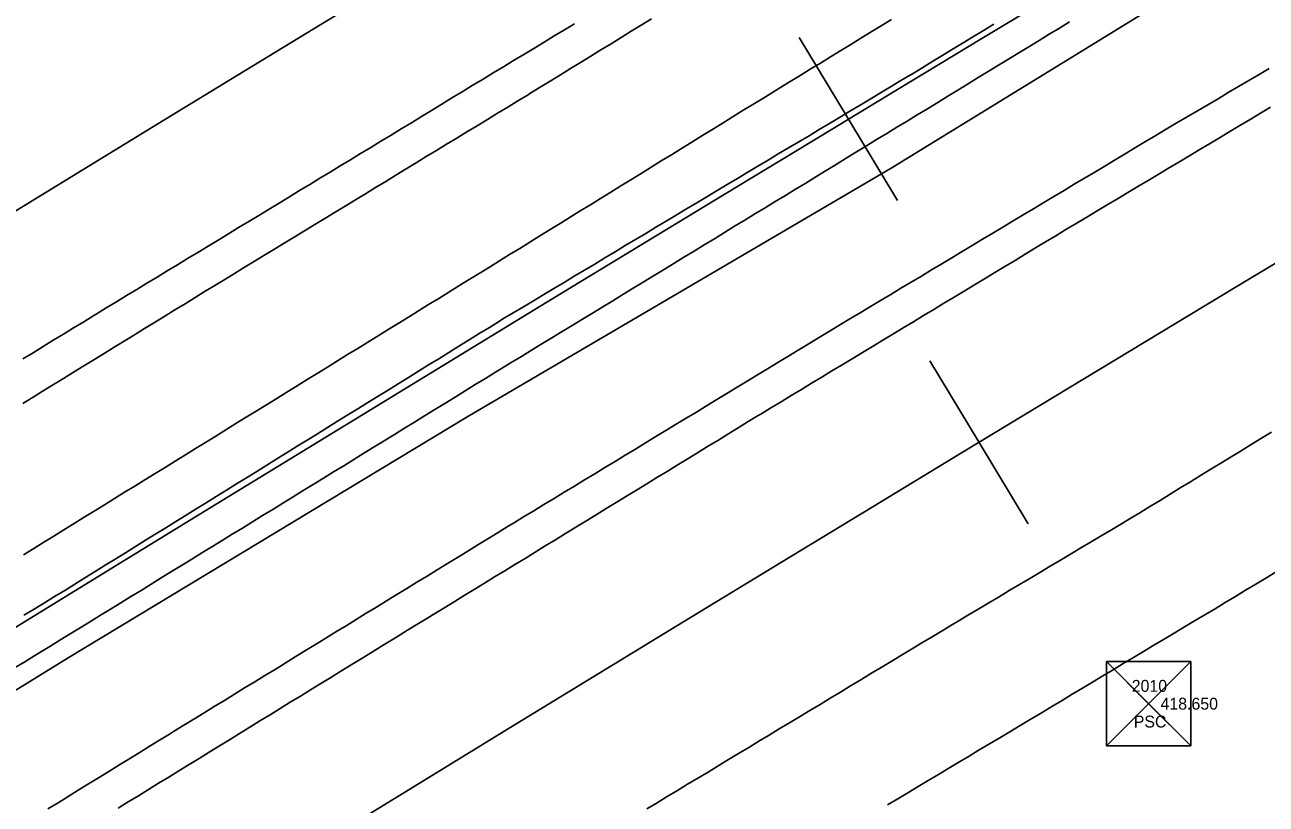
# Model space of a CAD drawing. Extents: x 1901471 to 1963503, y 756461 to 799997.
# Drawn here: x 1927939.3 to 1928043.7, y 772222.7 to 772288.2 of the extents above; entities that cross this region are included whole.
import ezdxf

# ---------------------------------------------------------------- set-up
doc = ezdxf.new("R2010")
doc.units = 0
for name, color, linetype in [('RD_EX_DR_ErosCtrl', 7, 'Continuous'), ('RD_EX_Fence_Other', 7, 'Continuous'), ('RD_EX_H2O', 7, 'Continuous'), ('RD_EX_Road', 7, 'Continuous'), ('RD_EX_Road_txCode', 7, 'Continuous'), ('RD_HC_Cl', 7, 'Continuous'), ('RD_HC_Data_Tic', 7, 'Continuous'), ('RD_HC_Survey', 7, 'Continuous'), ('RD_HC_txCode', 7, 'Continuous'), ('RD_SMD_Locator', 7, 'Continuous')]:
    doc.layers.add(name, color=color, linetype=linetype)

msp = doc.modelspace()

# ---------------------------------------------------------------- linework, layer by layer
at = {"layer": 'RD_EX_DR_ErosCtrl'}
for points in [[(1927938.43, 772234.12), (1927939.29, 772234.64), (1927940.14, 772235.16), (1927940.54, 772235.41), (1927941.39, 772235.93), (1927942.24, 772236.45), (1927943.1, 772236.98), (1927943.95, 772237.5), (1927944.8, 772238.03), (1927945.65, 772238.55), (1927946.5, 772239.07), (1927947.36, 772239.6), (1927948.21, 772240.12), (1927949.06, 772240.64), (1927949.91, 772241.17), (1927950.76, 772241.69), (1927951.61, 772242.22), (1927952.47, 772242.74), (1927953.32, 772243.26), (1927954.17, 772243.79), (1927955.02, 772244.31), (1927955.87, 772244.83), (1927956.73, 772245.36), (1927957.58, 772245.88), (1927957.58, 772245.88), (1927958.43, 772246.4), (1927959.28, 772246.93), (1927960.13, 772247.45), (1927960.99, 772247.98), (1927961.84, 772248.5), (1927962.69, 772249.02), (1927963.54, 772249.55), (1927964.39, 772250.07), (1927965.24, 772250.59), (1927966.1, 772251.12), (1927966.95, 772251.64), (1927967.8, 772252.17), (1927968.65, 772252.69), (1927969.5, 772253.21), (1927970.36, 772253.74), (1927971.21, 772254.26), (1927972.06, 772254.78), (1927972.91, 772255.31), (1927973.76, 772255.83), (1927974.61, 772256.35), (1927975.47, 772256.88), (1927976.32, 772257.4), (1927977.17, 772257.93), (1927978.02, 772258.45), (1927978.87, 772258.97), (1927979.73, 772259.5), (1927980.19, 772259.78), (1927981.05, 772260.3), (1927981.9, 772260.82), (1927982.75, 772261.35), (1927983.61, 772261.87), (1927984.46, 772262.39), (1927985.31, 772262.91), (1927986.17, 772263.43), (1927987.02, 772263.95), (1927987.88, 772264.47), (1927988.73, 772264.99), (1927989.58, 772265.51), (1927990.44, 772266.03), (1927991.29, 772266.55), (1927992.14, 772267.07), (1927993, 772267.59), (1927993.85, 772268.11), (1927994.7, 772268.64), (1927995.56, 772269.16), (1927996.41, 772269.68), (1927997.27, 772270.2), (1927998.12, 772270.72), (1927998.97, 772271.24), (1927999.83, 772271.76), (1928000.68, 772272.28), (1928001.53, 772272.8), (1928002.39, 772273.32), (1928003.24, 772273.84), (1928004.09, 772274.36), (1928004.95, 772274.88), (1928005.8, 772275.4), (1928006.66, 772275.93), (1928007.51, 772276.45), (1928008.36, 772276.97), (1928009.22, 772277.49), (1928010.07, 772278.01), (1928010.92, 772278.53), (1928011.78, 772279.05), (1928011.78, 772279.05), (1928012.63, 772279.57), (1928013.49, 772280.09), (1928014.34, 772280.61), (1928015.19, 772281.13), (1928016.05, 772281.65), (1928016.9, 772282.17), (1928017.75, 772282.69), (1928018.61, 772283.22), (1928019.46, 772283.74), (1928020.31, 772284.26), (1928021.17, 772284.78), (1928022.02, 772285.3), (1928022.88, 772285.82), (1928023.73, 772286.34), (1928024.58, 772286.86), (1928025.44, 772287.38), (1928026.29, 772287.9), (1928027.14, 772288.42)], [(1928012.16, 772288.62), (1928011.31, 772288.1), (1928010.46, 772287.58), (1928009.6, 772287.05), (1928008.75, 772286.53), (1928007.9, 772286.01), (1928007.05, 772285.49), (1928006.19, 772284.96), (1928005.34, 772284.44), (1928004.49, 772283.92), (1928003.64, 772283.4), (1928002.78, 772282.87), (1928001.93, 772282.35), (1928001.08, 772281.83), (1928000.22, 772281.31), (1927999.62, 772280.94), (1927998.77, 772280.41), (1927997.92, 772279.89), (1927997.07, 772279.36), (1927996.22, 772278.84), (1927995.37, 772278.31), (1927994.51, 772277.79), (1927993.66, 772277.26), (1927992.81, 772276.74), (1927991.96, 772276.21), (1927991.11, 772275.69), (1927990.26, 772275.16), (1927989.41, 772274.64), (1927988.56, 772274.11), (1927987.71, 772273.59), (1927986.86, 772273.06), (1927986, 772272.54), (1927985.15, 772272.01), (1927984.3, 772271.48), (1927983.45, 772270.96), (1927982.6, 772270.43), (1927981.75, 772269.91), (1927980.9, 772269.38), (1927980.05, 772268.86), (1927979.2, 772268.33), (1927978.35, 772267.81), (1927977.49, 772267.28), (1927976.64, 772266.76), (1927975.79, 772266.23), (1927974.94, 772265.71), (1927974.94, 772265.71), (1927974.09, 772265.18), (1927973.24, 772264.66), (1927972.39, 772264.13), (1927971.54, 772263.61), (1927970.69, 772263.08), (1927969.84, 772262.56), (1927968.99, 772262.03), (1927968.13, 772261.51), (1927967.28, 772260.98), (1927966.43, 772260.46), (1927965.58, 772259.93), (1927964.73, 772259.41), (1927963.88, 772258.88), (1927963.03, 772258.36), (1927962.18, 772257.83), (1927961.33, 772257.31), (1927960.48, 772256.78), (1927959.6, 772256.24), (1927958.74, 772255.71), (1927957.89, 772255.19), (1927957.04, 772254.66), (1927956.19, 772254.14), (1927955.34, 772253.61), (1927954.49, 772253.08), (1927953.64, 772252.56), (1927952.79, 772252.03), (1927951.94, 772251.51), (1927951.09, 772250.98), (1927950.24, 772250.46), (1927949.39, 772249.93), (1927948.53, 772249.41), (1927947.68, 772248.88), (1927946.83, 772248.36), (1927945.98, 772247.83), (1927945.13, 772247.31), (1927944.28, 772246.78), (1927943.43, 772246.25), (1927942.58, 772245.73), (1927941.73, 772245.2), (1927940.88, 772244.68), (1927940.03, 772244.15), (1927939.18, 772243.63)]]:
    msp.add_lwpolyline(points, dxfattribs=at)
at = {"layer": 'RD_EX_Fence_Other'}
msp.add_lwpolyline([(1928044.45, 772295.99), (1928012.14, 772276.14), (1927976.55, 772255.25), (1927942.93, 772234.97), (1927904.44, 772211.24), (1927860.79, 772184), (1927819.19, 772158.23), (1927779.32, 772132.86), (1927734.82, 772104.62), (1927691.68, 772076.4), (1927643.49, 772044.02), (1927625.68, 772031.98), (1927589.77, 772008.73), (1927546.28, 771980.95), (1927496.16, 771947.6), (1927452.51, 771918.77), (1927408.3, 771889.28), (1927363.99, 771859.73), (1927324.38, 771833.09), (1927282.02, 771804.91), (1927242.96, 771779.23), (1927193.2, 771746.24), (1927217.15, 771765.53), (1927225.9, 771773.24)], dxfattribs=at)
at = {"layer": 'RD_EX_H2O'}
msp.add_lwpolyline([(1927939.21, 772238.54), (1927940.07, 772239.06), (1927940.94, 772239.59), (1927941.79, 772240.12), (1927942.64, 772240.64), (1927943.49, 772241.17), (1927944.34, 772241.69), (1927945.19, 772242.22), (1927946.04, 772242.75), (1927946.89, 772243.27), (1927947.74, 772243.8), (1927948.59, 772244.33), (1927949.44, 772244.85), (1927950.29, 772245.38), (1927951.14, 772245.9), (1927951.99, 772246.43), (1927952.84, 772246.96), (1927953.69, 772247.48), (1927954.54, 772248.01), (1927955.39, 772248.54), (1927956.24, 772249.06), (1927956.24, 772249.06), (1927957.09, 772249.59), (1927957.94, 772250.11), (1927958.79, 772250.64), (1927959.64, 772251.17), (1927960.49, 772251.69), (1927961.34, 772252.22), (1927962.19, 772252.75), (1927963.04, 772253.27), (1927963.89, 772253.8), (1927964.74, 772254.32), (1927965.59, 772254.85), (1927966.44, 772255.38), (1927967.29, 772255.9), (1927968.14, 772256.43), (1927968.99, 772256.95), (1927969.84, 772257.48), (1927970.69, 772258.01), (1927971.54, 772258.53), (1927972.39, 772259.06), (1927973.24, 772259.59), (1927974.09, 772260.11), (1927974.94, 772260.64), (1927975.79, 772261.16), (1927976.65, 772261.69), (1927977.5, 772262.22), (1927978.35, 772262.74), (1927979.2, 772263.27), (1927979.49, 772263.45), (1927980.35, 772263.96), (1927981.21, 772264.48), (1927982.06, 772264.99), (1927982.92, 772265.51), (1927983.78, 772266.02), (1927984.64, 772266.53), (1927985.49, 772267.05), (1927986.35, 772267.56), (1927987.21, 772268.07), (1927988.07, 772268.59), (1927988.93, 772269.1), (1927989.78, 772269.62), (1927990.64, 772270.13), (1927991.5, 772270.64), (1927992.36, 772271.16), (1927993.22, 772271.67), (1927994.07, 772272.18), (1927994.93, 772272.7), (1927995.79, 772273.21), (1927996.65, 772273.73), (1927997.51, 772274.24), (1927998.36, 772274.75), (1927999.22, 772275.27), (1928000.08, 772275.78), (1928000.94, 772276.29), (1928001.8, 772276.81), (1928002.65, 772277.32), (1928003.51, 772277.83), (1928004.37, 772278.35), (1928005.23, 772278.86), (1928006.09, 772279.38), (1928006.94, 772279.89), (1928007.8, 772280.4), (1928008.66, 772280.92), (1928009.52, 772281.43), (1928010.37, 772281.94), (1928010.37, 772281.94), (1928011.23, 772282.46), (1928012.09, 772282.97), (1928012.95, 772283.49), (1928013.81, 772284), (1928013.93, 772284.07), (1928014.79, 772284.59), (1928015.64, 772285.11), (1928016.49, 772285.63), (1928017.35, 772286.15), (1928018.2, 772286.67), (1928019.06, 772287.19), (1928019.91, 772287.71), (1928020.76, 772288.23)], dxfattribs=at)
at = {"layer": 'RD_EX_Road'}
for points in [[(1927939.13, 772256.35), (1927939.98, 772256.88), (1927940.83, 772257.4), (1927941.69, 772257.93), (1927942.54, 772258.45), (1927943.39, 772258.97), (1927944.24, 772259.5), (1927945.09, 772260.02), (1927945.95, 772260.54), (1927946.8, 772261.07), (1927947.65, 772261.59), (1927948.5, 772262.12), (1927949.35, 772262.64), (1927950.2, 772263.16), (1927951.06, 772263.69), (1927951.91, 772264.21), (1927952.76, 772264.73), (1927953.61, 772265.26), (1927954.46, 772265.78), (1927955.12, 772266.18), (1927955.97, 772266.7), (1927956.83, 772267.22), (1927957.68, 772267.74), (1927958.53, 772268.26), (1927959.39, 772268.78), (1927960.24, 772269.3), (1927961.1, 772269.82), (1927961.95, 772270.34), (1927962.81, 772270.86), (1927963.66, 772271.38), (1927964.51, 772271.9), (1927965.37, 772272.42), (1927966.22, 772272.94), (1927967.08, 772273.46), (1927967.93, 772273.98), (1927968.78, 772274.5), (1927969.64, 772275.02), (1927970.49, 772275.54), (1927971.35, 772276.06), (1927972.2, 772276.58), (1927973.05, 772277.1), (1927973.91, 772277.62), (1927974.76, 772278.14), (1927975.62, 772278.66), (1927976.47, 772279.18), (1927977.33, 772279.7), (1927978.18, 772280.22), (1927979.03, 772280.74), (1927979.89, 772281.26), (1927980.74, 772281.78), (1927981.6, 772282.3), (1927981.76, 772282.4), (1927982.62, 772282.93), (1927983.47, 772283.45), (1927984.32, 772283.97), (1927985.17, 772284.5), (1927986.02, 772285.02), (1927986.87, 772285.54), (1927987.73, 772286.07), (1927988.58, 772286.59), (1927989.43, 772287.12), (1927990.28, 772287.64), (1927991.13, 772288.16), (1927991.99, 772288.69)], [(1927939.13, 772260.09), (1927939.98, 772260.61), (1927940.83, 772261.13), (1927941.68, 772261.66), (1927942.54, 772262.18), (1927943.39, 772262.7), (1927944.24, 772263.22), (1927945.1, 772263.74), (1927945.29, 772263.86), (1927946.14, 772264.38), (1927947, 772264.9), (1927947.85, 772265.42), (1927948.71, 772265.94), (1927949.56, 772266.45), (1927950.42, 772266.97), (1927951.27, 772267.49), (1927952.13, 772268.01), (1927952.98, 772268.53), (1927953.84, 772269.05), (1927954.69, 772269.57), (1927955.55, 772270.09), (1927956.4, 772270.61), (1927957.26, 772271.13), (1927958.11, 772271.65), (1927958.97, 772272.16), (1927959.82, 772272.68), (1927960.67, 772273.2), (1927961.53, 772273.72), (1927962.38, 772274.24), (1927963.24, 772274.76), (1927964.09, 772275.28), (1927964.95, 772275.8), (1927965.8, 772276.32), (1927966.66, 772276.84), (1927967.51, 772277.36), (1927968.37, 772277.87), (1927969.22, 772278.39), (1927970.08, 772278.91), (1927970.93, 772279.43), (1927971.79, 772279.95), (1927972.64, 772280.47), (1927973.49, 772280.99), (1927974.35, 772281.51), (1927975.2, 772282.03), (1927976.06, 772282.55), (1927976.91, 772283.07), (1927977.82, 772283.61), (1927978.67, 772284.13), (1927979.53, 772284.65), (1927980.38, 772285.17), (1927981.24, 772285.68), (1927982.09, 772286.2), (1927982.95, 772286.72), (1927983.81, 772287.24), (1927984.66, 772287.75), (1927985.52, 772288.27)], [(1927941.23, 772222.27), (1927942.08, 772222.79), (1927942.93, 772223.32), (1927943.78, 772223.84), (1927944.64, 772224.37), (1927945.49, 772224.89), (1927946.34, 772225.41), (1927947.19, 772225.94), (1927948.04, 772226.46), (1927948.89, 772226.99), (1927949.75, 772227.51), (1927950.6, 772228.04), (1927951.45, 772228.56), (1927951.8, 772228.78), (1927952.66, 772229.3), (1927953.51, 772229.82), (1927954.36, 772230.34), (1927955.21, 772230.87), (1927956.07, 772231.39), (1927956.92, 772231.91), (1927957.77, 772232.44), (1927958.62, 772232.96), (1927959.48, 772233.48), (1927960.33, 772234), (1927961.18, 772234.53), (1927962.03, 772235.05), (1927962.89, 772235.57), (1927963.74, 772236.09), (1927964.59, 772236.62), (1927965.44, 772237.14), (1927966.3, 772237.66), (1927967.15, 772238.19), (1927968, 772238.71), (1927968.85, 772239.23), (1927969.71, 772239.75), (1927970.56, 772240.28), (1927971.41, 772240.8), (1927972.26, 772241.32), (1927973.12, 772241.84), (1927973.97, 772242.37), (1927974.82, 772242.89), (1927975.67, 772243.41), (1927976.53, 772243.93), (1927977.38, 772244.46), (1927978.23, 772244.98), (1927979.08, 772245.5), (1927979.94, 772246.03), (1927980.38, 772246.29), (1927981.23, 772246.81), (1927982.09, 772247.33), (1927982.94, 772247.85), (1927983.8, 772248.37), (1927984.65, 772248.89), (1927985.51, 772249.41), (1927986.36, 772249.93), (1927987.22, 772250.44), (1927988.07, 772250.96), (1927988.93, 772251.48), (1927989.78, 772252), (1927990.64, 772252.52), (1927991.49, 772253.04), (1927992.34, 772253.56), (1927993.2, 772254.08), (1927994.05, 772254.6), (1927994.91, 772255.12), (1927995.76, 772255.63), (1927996.62, 772256.15), (1927997.47, 772256.67), (1927998.33, 772257.19), (1927999.18, 772257.71), (1928000.04, 772258.23), (1928000.89, 772258.75), (1928001.75, 772259.27), (1928002.6, 772259.79), (1928003.46, 772260.3), (1928004.31, 772260.82), (1928005.17, 772261.34), (1928006.02, 772261.86), (1928006.88, 772262.38), (1928007.73, 772262.9), (1928008.67, 772263.46), (1928009.53, 772263.98), (1928010.39, 772264.49), (1928011.24, 772265), (1928012.1, 772265.52), (1928012.96, 772266.03), (1928013.82, 772266.55), (1928014.68, 772267.06), (1928015.53, 772267.58), (1928016.39, 772268.09), (1928017.25, 772268.6), (1928018.11, 772269.12), (1928018.96, 772269.63), (1928019.82, 772270.15), (1928020.68, 772270.66), (1928021.54, 772271.17), (1928022.39, 772271.69), (1928023.25, 772272.2), (1928024.11, 772272.72), (1928024.97, 772273.23), (1928025.83, 772273.74), (1928026.68, 772274.26), (1928027.54, 772274.77), (1928028.4, 772275.29), (1928029.26, 772275.8), (1928030.11, 772276.31), (1928030.97, 772276.83), (1928031.83, 772277.34), (1928032.69, 772277.86), (1928033.54, 772278.37), (1928034.4, 772278.88), (1928035.26, 772279.4), (1928036.12, 772279.91), (1928037.04, 772280.45), (1928037.9, 772280.96), (1928038.77, 772281.46), (1928039.63, 772281.97), (1928040.49, 772282.48), (1928041.35, 772282.98), (1928042.22, 772283.49), (1928043.08, 772283.99), (1928043.94, 772284.5)], [(1927947.13, 772222.32), (1927947.98, 772222.85), (1927948.84, 772223.37), (1927949.69, 772223.89), (1927950.54, 772224.42), (1927951.39, 772224.94), (1927952.24, 772225.46), (1927953.1, 772225.99), (1927953.95, 772226.51), (1927954.8, 772227.04), (1927955.65, 772227.56), (1927956.5, 772228.08), (1927957.35, 772228.61), (1927958.21, 772229.13), (1927959.06, 772229.66), (1927959.91, 772230.18), (1927960.76, 772230.7), (1927961.61, 772231.23), (1927962.47, 772231.75), (1927963.32, 772232.27), (1927964.17, 772232.8), (1927965.02, 772233.32), (1927965.87, 772233.85), (1927966.73, 772234.37), (1927967.58, 772234.89), (1927968.43, 772235.42), (1927969.28, 772235.94), (1927970.13, 772236.46), (1927970.98, 772236.99), (1927971.11, 772237.07), (1927971.97, 772237.59), (1927972.82, 772238.11), (1927973.67, 772238.63), (1927974.52, 772239.15), (1927975.38, 772239.68), (1927976.23, 772240.2), (1927977.08, 772240.72), (1927977.94, 772241.24), (1927978.79, 772241.77), (1927979.64, 772242.29), (1927980.49, 772242.81), (1927981.35, 772243.33), (1927982.2, 772243.85), (1927983.05, 772244.38), (1927983.91, 772244.9), (1927984.76, 772245.42), (1927985.61, 772245.94), (1927986.46, 772246.46), (1927987.32, 772246.99), (1927988.17, 772247.51), (1927989.02, 772248.03), (1927989.88, 772248.55), (1927990.73, 772249.07), (1927991.58, 772249.6), (1927992.43, 772250.12), (1927993.29, 772250.64), (1927994.14, 772251.16), (1927994.99, 772251.68), (1927995.85, 772252.21), (1927996.7, 772252.73), (1927997.55, 772253.25), (1927998.4, 772253.77), (1927999.26, 772254.29), (1928000.11, 772254.82), (1928000.96, 772255.34), (1928001.17, 772255.46), (1928002.02, 772255.98), (1928002.88, 772256.49), (1928003.73, 772257.01), (1928004.59, 772257.53), (1928005.45, 772258.05), (1928006.3, 772258.56), (1928007.16, 772259.08), (1928008.01, 772259.6), (1928008.87, 772260.11), (1928009.73, 772260.63), (1928010.58, 772261.15), (1928011.44, 772261.66), (1928012.29, 772262.18), (1928013.15, 772262.7), (1928014.01, 772263.21), (1928014.86, 772263.73), (1928015.72, 772264.25), (1928016.57, 772264.77), (1928017.43, 772265.28), (1928018.28, 772265.8), (1928019.14, 772266.32), (1928020, 772266.83), (1928020.85, 772267.35), (1928021.71, 772267.87), (1928022.56, 772268.38), (1928023.42, 772268.9), (1928024.28, 772269.42), (1928025.13, 772269.93), (1928025.99, 772270.45), (1928026.84, 772270.97), (1928027.7, 772271.49), (1928028.6, 772272.02), (1928029.45, 772272.53), (1928030.31, 772273.05), (1928031.17, 772273.56), (1928032.03, 772274.07), (1928032.89, 772274.59), (1928033.75, 772275.1), (1928034.6, 772275.61), (1928035.46, 772276.12), (1928036.32, 772276.64), (1928037.18, 772277.15), (1928038.04, 772277.66), (1928038.9, 772278.18), (1928039.75, 772278.69), (1928040.61, 772279.2), (1928041.47, 772279.72), (1928042.33, 772280.23), (1928043.19, 772280.74), (1928044.05, 772281.25)], [(1928044.13, 772253.95), (1928043.27, 772253.43), (1928042.42, 772252.91), (1928041.57, 772252.38), (1928040.72, 772251.86), (1928039.86, 772251.34), (1928039.01, 772250.82), (1928038.16, 772250.29), (1928037.31, 772249.77), (1928036.45, 772249.25), (1928035.6, 772248.73), (1928034.75, 772248.2), (1928033.9, 772247.68), (1928033.04, 772247.16), (1928032.38, 772246.75), (1928031.52, 772246.24), (1928030.67, 772245.73), (1928029.81, 772245.22), (1928028.95, 772244.71), (1928028.09, 772244.2), (1928027.23, 772243.68), (1928026.37, 772243.17), (1928025.51, 772242.66), (1928024.65, 772242.15), (1928023.79, 772241.64), (1928022.93, 772241.13), (1928022.07, 772240.62), (1928021.21, 772240.1), (1928020.35, 772239.59), (1928019.5, 772239.08), (1928018.64, 772238.57), (1928017.78, 772238.06), (1928017.29, 772237.77), (1928016.43, 772237.25), (1928015.58, 772236.73), (1928014.72, 772236.22), (1928013.86, 772235.7), (1928013.01, 772235.18), (1928012.15, 772234.67), (1928011.29, 772234.15), (1928010.44, 772233.64), (1928009.58, 772233.12), (1928008.73, 772232.6), (1928007.87, 772232.09), (1928007.01, 772231.57), (1928006.16, 772231.05), (1928005.3, 772230.54), (1928004.44, 772230.02), (1928003.59, 772229.5), (1928002.73, 772228.99), (1928001.87, 772228.47), (1928001.02, 772227.96), (1928000.16, 772227.44), (1927999.31, 772226.92), (1927998.45, 772226.41), (1927997.59, 772225.89), (1927996.74, 772225.37), (1927995.88, 772224.86), (1927995.02, 772224.34), (1927994.17, 772223.82), (1927993.31, 772223.31), (1927992.46, 772222.79), (1927991.6, 772222.28)], [(1928044.52, 772242.19), (1928043.66, 772241.67), (1928042.81, 772241.16), (1928041.95, 772240.65), (1928041.09, 772240.13), (1928040.23, 772239.62), (1928039.38, 772239.1), (1928038.52, 772238.59), (1928037.66, 772238.07), (1928036.8, 772237.56), (1928035.95, 772237.05), (1928035.09, 772236.53), (1928034.23, 772236.02), (1928033.37, 772235.5), (1928032.52, 772234.99), (1928031.66, 772234.48), (1928030.8, 772233.96), (1928029.94, 772233.45), (1928029.08, 772232.93), (1928028.23, 772232.42), (1928027.37, 772231.9), (1928026.51, 772231.39), (1928025.65, 772230.88), (1928025.56, 772230.82), (1928024.7, 772230.3), (1928023.84, 772229.79), (1928022.98, 772229.28), (1928022.13, 772228.76), (1928021.27, 772228.25), (1928020.41, 772227.74), (1928019.55, 772227.22), (1928018.69, 772226.71), (1928017.84, 772226.2), (1928016.98, 772225.68), (1928016.12, 772225.17), (1928015.26, 772224.66), (1928014.4, 772224.14), (1928013.55, 772223.63), (1928012.69, 772223.11), (1928011.83, 772222.6)]]:
    msp.add_lwpolyline(points, dxfattribs=at)
at = {"layer": 'RD_HC_Cl'}
for centre, radius, start, end in [((1933934.02, 762479.74), 11482.38, 112.01316, 122.84589), ((1933920.67, 762509.14), 11420.5, 112.014247, 122.846378), ((1933910.03, 762523.4), 11373.86, 112.013249, 123.541888)]:
    msp.add_arc(centre, radius, start, end, dxfattribs=at)
at = {"layer": 'RD_HC_Data_Tic'}
for p, q in [((1928008.54, 772280.26), (1928004.4, 772287.1)), ((1928008.54, 772280.26), (1928012.68, 772273.41)), ((1928019.53, 772253.08), (1928015.39, 772259.93)), ((1928019.53, 772253.08), (1928023.67, 772246.24))]:
    msp.add_line(p, q, dxfattribs=at)
at = {"layer": 'RD_HC_Survey'}
for p, q in [((1928030.26, 772234.65), (1928037.33, 772227.58)), ((1928037.33, 772234.65), (1928030.26, 772227.58)), ((1928037.33, 772234.65), (1928030.26, 772234.65)), ((1928030.26, 772234.65), (1928033.79, 772231.11)), ((1928033.79, 772231.11), (1928037.33, 772234.65)), ((1928033.79, 772231.11), (1928030.26, 772227.58)), ((1928037.33, 772227.58), (1928033.79, 772231.11)), ((1928030.26, 772227.58), (1928037.33, 772227.58))]:
    msp.add_line(p, q, dxfattribs=at)
msp.add_lwpolyline([(1928037.33, 772234.65), (1928030.26, 772234.65), (1928030.26, 772227.58), (1928037.33, 772227.58)], close=True, dxfattribs=at)
at = {"layer": 'RD_SMD_Locator'}
msp.add_circle((1928033.79, 772231.11), 0.001, dxfattribs=at)

# ---------------------------------------------------------------- texts
at = {"layer": 'RD_EX_Road_txCode'}
msp.add_text('418.650', height=1, dxfattribs=at).set_placement((1928034.79, 772230.61))
at = {"layer": 'RD_HC_txCode'}
for s, p in [('2010', (1928032.37, 772232.11)), ('PSC', (1928032.54, 772229.11))]:
    msp.add_text(s, height=1, dxfattribs=at).set_placement(p)

doc.saveas('drawing.dxf')
